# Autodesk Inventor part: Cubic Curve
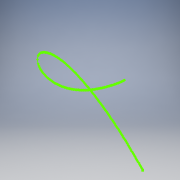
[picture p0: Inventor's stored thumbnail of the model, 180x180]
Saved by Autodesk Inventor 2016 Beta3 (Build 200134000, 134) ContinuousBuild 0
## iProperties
Created: 2008-02
Part Number: Cubic Curve
Document SubType Name: Modeling
Designer: Autodesk, Inc.
Density: 1 g/cm^3
Material: Generic
Appearance: Default
Author: Autodesk, Inc.
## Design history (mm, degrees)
sketch "Sketch1"
  geometry: 301 further points
  constraints: 301 other
